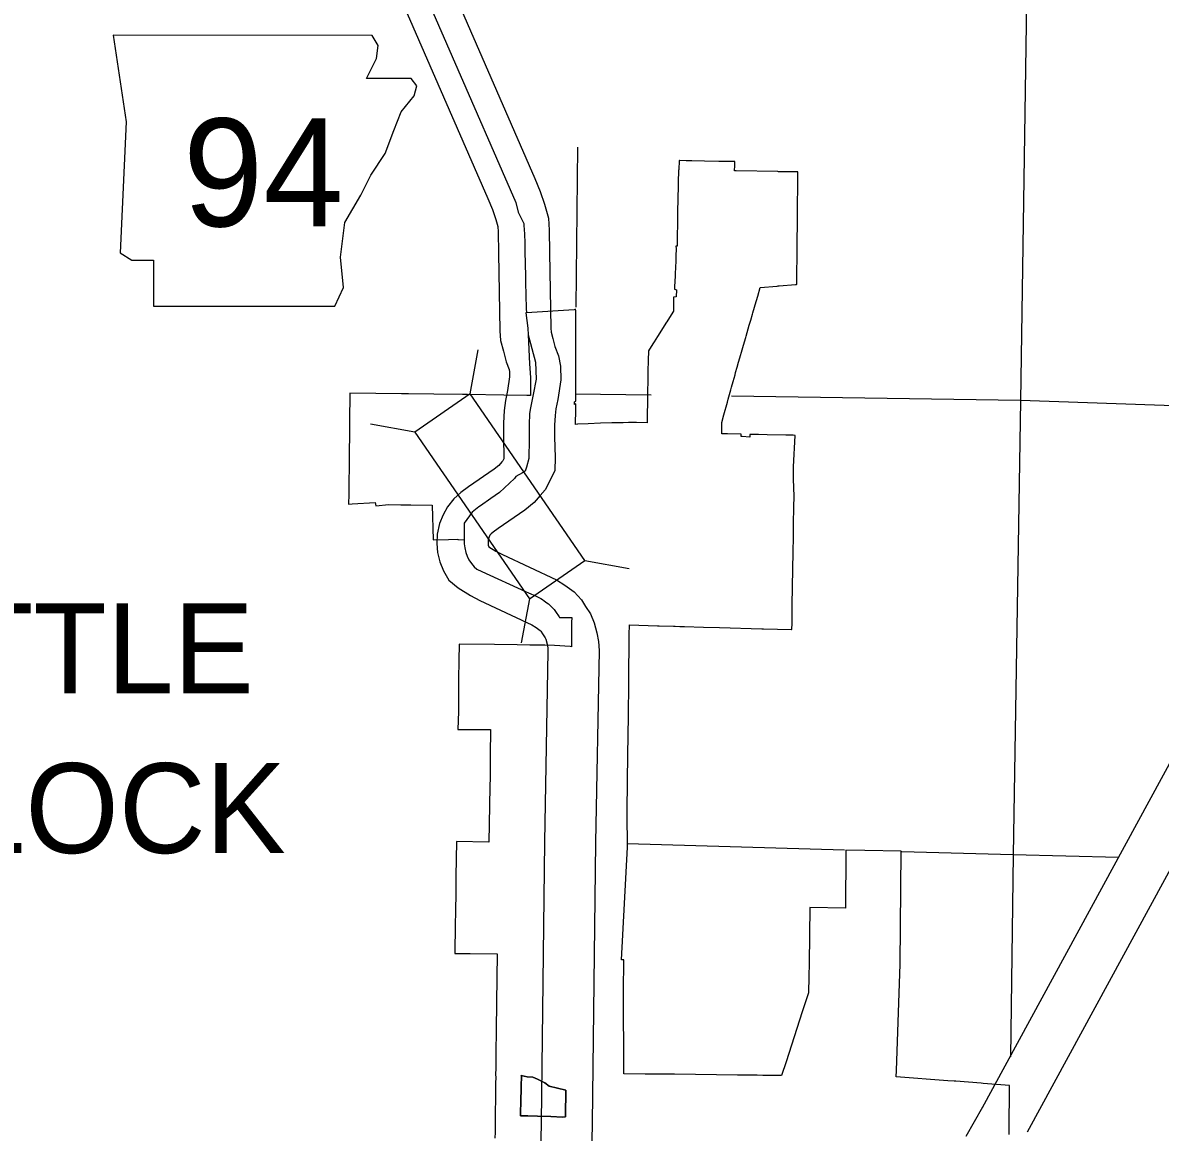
# Model space of a CAD drawing. Extents: x 309389.3 to 309420.2, y 336441.4 to 336461.2.
# Drawn here: x 309392.47 to 309393.483, y 336458.352 to 336459.339 of the extents above; entities that cross this region are included whole.
import ezdxf

# ---------------------------------------------------------------- set-up
doc = ezdxf.new("R2010")
doc.units = 0
for name, color, linetype in [('Level 24', 7, 'Continuous'), ('Level 37', 7, 'Continuous'), ('Level 4', 7, 'Continuous'), ('Level 48', 7, 'Continuous'), ('Level 62', 7, 'Continuous'), ('R_Axis Annot', 7, 'Continuous'), ('R_Contours', 7, 'Continuous')]:
    doc.layers.add(name, color=color, linetype=linetype)

msp = doc.modelspace()

# ---------------------------------------------------------------- linework, layer by layer
at = {"layer": 'Level 24'}
for points in [[(309392.8477, 336459.3808), (309392.9261, 336459.2006), (309392.9308, 336459.1891), (309392.9346, 336459.178), (309392.9382, 336459.1655), (309392.9387, 336459.1547), (309392.9391, 336459.1349), (309392.9403, 336459.0674), (309392.9406, 336459.0639), (309392.942, 336459.0584), (309392.9439, 336459.0513), (309392.947, 336459.0429), (309392.9488, 336459.0337), (309392.9492, 336459.0216), (309392.9465, 336459.004), (309392.9448, 336458.9957), (309392.9441, 336458.9897), (309392.9435, 336458.9813), (309392.9435, 336458.9709), (309392.944, 336458.9524), (309392.9439, 336458.9408), (309392.9395, 336458.9315), (309392.9353, 336458.9236), (309392.9309, 336458.9185), (309392.9255, 336458.9124), (309392.9171, 336458.9056), (309392.8933, 336458.8893), (309392.8889, 336458.886), (309392.8871, 336458.8844), (309392.8861, 336458.8832), (309392.8854, 336458.8817), (309392.8847, 336458.8801), (309392.8844, 336458.879), (309392.8844, 336458.8765), (309392.8845, 336458.8746), (309392.8845, 336458.8743), (309392.8851, 336458.8729), (309392.8913, 336458.8691), (309392.8971, 336458.8661), (309392.9454, 336458.8434), (309392.9528, 336458.8387), (309392.9609, 336458.8329), (309392.9677, 336458.8256), (309392.9712, 336458.8199), (309392.9756, 336458.8132), (309392.9787, 336458.8053), (309392.9813, 336458.7964), (309392.9827, 336458.7886), (309392.9832, 336458.7807), (309392.9799, 336458.6098), (309392.977, 336458.3599)], [(309392.8054, 336459.3642), (309392.8842, 336459.183), (309392.8882, 336459.1731), (309392.8912, 336459.1643), (309392.893, 336459.158), (309392.8933, 336459.1531), (309392.8936, 336459.1341), (309392.8949, 336459.0651), (309392.8956, 336459.0564), (309392.898, 336459.0469), (309392.9005, 336459.0376), (309392.9031, 336459.0306), (309392.9035, 336459.0286), (309392.9036, 336459.0243), (309392.9017, 336459.0119), (309392.9, 336459.0031), (309392.8988, 336458.9942), (309392.8981, 336458.9829), (309392.898, 336458.9703), (309392.8985, 336458.9521), (309392.8985, 336458.9513), (309392.8976, 336458.9495), (309392.8967, 336458.9485), (309392.894, 336458.9454), (309392.8899, 336458.9421), (309392.8671, 336458.9263), (309392.8601, 336458.9213), (309392.8538, 336458.9155), (309392.8482, 336458.9085), (309392.8443, 336458.9014), (309392.8411, 336458.8936), (309392.8391, 336458.8843), (309392.8389, 336458.8759), (309392.8393, 336458.8678), (309392.8414, 336458.8596), (309392.8448, 336458.8517), (309392.8496, 336458.8432), (309392.8579, 336458.8363), (309392.8689, 336458.8295), (309392.8771, 336458.8253), (309392.9234, 336458.8035), (309392.9273, 336458.8011), (309392.9307, 336458.7985), (309392.9313, 336458.798), (309392.9327, 336458.7956), (309392.9351, 336458.792), (309392.9357, 336458.7906), (309392.9369, 336458.7862), (309392.9375, 336458.7831), (309392.9377, 336458.7797), (309392.9345, 336458.6105), (309392.9316, 336458.3605)], [(309392.9316, 336458.3606), (309392.9286, 336458.2087), (309392.9262, 336458.0086), (309392.9229, 336457.8315)], [(309392.977, 336458.3597), (309392.9741, 336458.208), (309392.9716, 336458.0079), (309392.9688, 336457.8526)]]:
    msp.add_lwpolyline(points, dxfattribs=at)
at = {"layer": 'Level 37'}
for p, q in [((309392.8685, 336459.009), (309392.8757, 336459.0483)), ((309392.8191, 336458.975), (309392.7797, 336458.9822)), ((309392.9706, 336458.8608), (309393.0099, 336458.8536)), ((309392.9212, 336458.8267), (309392.914, 336458.7874))]:
    msp.add_line(p, q, dxfattribs=at)
msp.add_lwpolyline([(309392.8191, 336458.975), (309392.9212, 336458.8267), (309392.9706, 336458.8608), (309392.8685, 336459.009)], close=True, dxfattribs=at)
at = {"layer": 'Level 4'}
for points in [[(309393.3657, 336459.536), (309393.3641, 336459.3975), (309393.3582, 336459.0027), (309393.3517, 336458.5988), (309393.3493, 336458.4192)], [(309393.0295, 336459.008), (309392.962, 336459.0089)], [(309393.6565, 336458.9928), (309393.3584, 336459.0032), (309393.1011, 336459.0069)], [(309393.0083, 336458.6089), (309393.2016, 336458.6034)], [(309393.2527, 336458.6019), (309393.3515, 336458.5991), (309393.4458, 336458.5966)]]:
    msp.add_lwpolyline(points, dxfattribs=at)
at = {"layer": 'Level 48'}
msp.add_lwpolyline([(309392.9629, 336459.0863), (309392.9643, 336459.2285)], dxfattribs=at)
at = {"layer": 'Level 62'}
for points in [[(309392.8353, 336459.3487), (309392.8524, 336459.3093), (309392.909, 336459.1793), (309392.9113, 336459.1707), (309392.9162, 336459.1607), (309392.9161, 336459.1604), (309392.9163, 336459.1583), (309392.9165, 336459.1559), (309392.9166, 336459.1549), (309392.9167, 336459.1515), (309392.917, 336459.1431), (309392.9172, 336459.1336), (309392.9174, 336459.1267), (309392.9177, 336459.1118), (309392.9178, 336459.1081), (309392.918, 336459.0969), (309392.9182, 336459.0849), (309392.9185, 336459.0812), (309392.9181, 336459.0812), (309392.9197, 336459.0676), (309392.9202, 336459.0617), (309392.9212, 336459.0358), (309392.9223, 336459.0235), (309392.9221, 336459.0077), (309392.919, 336459.0077), (309392.8985, 336459.008), (309392.866, 336459.0084), (309392.8616, 336459.0085), (309392.836, 336459.0088), (309392.8137, 336459.0091), (309392.8073, 336459.0092), (309392.7846, 336459.0095), (309392.7615, 336459.0098), (309392.7612, 336458.9845), (309392.7607, 336458.9455), (309392.7605, 336458.929), (309392.7604, 336458.924), (309392.7604, 336458.9199), (309392.7602, 336458.911), (309392.7634, 336458.9111), (309392.7838, 336458.9124), (309392.7846, 336458.9095), (309392.796, 336458.9105), (309392.8069, 336458.9104), (309392.8121, 336458.9103), (309392.8158, 336458.9103), (309392.8345, 336458.9101), (309392.8354, 336458.8791), (309392.8492, 336458.8794), (309392.8574, 336458.8796), (309392.8574, 336458.8793), (309392.8631, 336458.8791), (309392.8631, 336458.8757), (309392.8636, 336458.8721), (309392.8645, 336458.8679), (309392.8658, 336458.8646), (309392.8674, 336458.8614), (309392.8696, 336458.858), (309392.8721, 336458.8551), (309392.8745, 336458.8531), (309392.8787, 336458.851), (309392.9177, 336458.8333), (309392.9205, 336458.8321), (309392.9226, 336458.8311), (309392.9252, 336458.83), (309392.9273, 336458.829), (309392.9301, 336458.8276), (309392.9315, 336458.8268), (309392.9328, 336458.8261), (309392.9344, 336458.825), (309392.9356, 336458.8241), (309392.9368, 336458.8232), (309392.9381, 336458.8221), (309392.9393, 336458.8211), (309392.9404, 336458.82), (309392.9415, 336458.8189), (309392.9424, 336458.8179), (309392.9431, 336458.8171), (309392.9438, 336458.8163), (309392.9445, 336458.8153), (309392.9457, 336458.8137), (309392.9466, 336458.8124), (309392.9476, 336458.8107), (309392.948, 336458.81), (309392.9589, 336458.81), (309392.9588, 336458.8056), (309392.9588, 336458.8053), (309392.9587, 336458.7954), (309392.9587, 336458.7935), (309392.9586, 336458.7838), (309392.9574, 336458.7842), (309392.9434, 336458.7852), (309392.935, 336458.7853), (309392.9217, 336458.7855), (309392.9103, 336458.7856)], [(309393.1564, 336458.8951), (309393.1566, 336458.9063), (309393.1566, 336458.9084), (309393.1568, 336458.9176), (309393.1562, 336458.9334), (309393.1563, 336458.9442), (309393.1576, 336458.9721), (309393.156, 336458.9722), (309393.1494, 336458.9723), (309393.1328, 336458.9727), (309393.1252, 336458.9728), (309393.1173, 336458.973), (309393.1173, 336458.9706), (309393.1105, 336458.971), (309393.1096, 336458.9711), (309393.1097, 336458.9733), (309393.0975, 336458.9735), (309393.0925, 336458.9735), (309393.0924, 336458.9781), (309393.0924, 336458.979), (309393.0924, 336458.9835), (309393.0943, 336458.9904), (309393.0974, 336459.0016), (309393.0981, 336459.0043), (309393.1004, 336459.0126), (309393.101, 336459.0151), (309393.1025, 336459.0201), (309393.1042, 336459.0261), (309393.1047, 336459.028), (309393.1061, 336459.0327), (309393.1074, 336459.0371), (309393.1084, 336459.041), (309393.1105, 336459.0482), (309393.1117, 336459.0523), (309393.1137, 336459.0592), (309393.1141, 336459.0604), (309393.116, 336459.067), (309393.1169, 336459.0702), (309393.1182, 336459.0746), (309393.1197, 336459.0799), (309393.1201, 336459.0811), (309393.123, 336459.0913), (309393.1233, 336459.0921), (309393.1244, 336459.096), (309393.1266, 336459.1038), (309393.127, 336459.1038), (309393.1414, 336459.105), (309393.1417, 336459.105), (309393.1427, 336459.1051), (309393.143, 336459.1052), (309393.1436, 336459.1052), (309393.158, 336459.1063), (309393.1584, 336459.1064), (309393.1587, 336459.1065), (309393.1589, 336459.1065), (309393.1592, 336459.1066), (309393.1596, 336459.1412), (309393.1596, 336459.1416), (309393.1599, 336459.1639), (309393.1601, 336459.2065), (309393.1589, 336459.2065), (309393.1586, 336459.2065), (309393.1559, 336459.2065), (309393.1434, 336459.2067), (309393.1429, 336459.2067), (309393.1423, 336459.2068), (309393.1052, 336459.2074), (309393.1038, 336459.2074), (309393.1038, 336459.2094), (309393.1039, 336459.2105), (309393.104, 336459.2157), (309393.1036, 336459.2157), (309393.0898, 336459.2159), (309393.077, 336459.2162), (309393.0657, 336459.2164), (309393.0606, 336459.2165), (309393.0548, 336459.2166), (309393.0544, 336459.2166), (309393.0541, 336459.2084), (309393.054, 336459.2081), (309393.0537, 336459.1971), (309393.0536, 336459.1968), (309393.0536, 336459.1943), (309393.0536, 336459.1939), (309393.0536, 336459.1931), (309393.0534, 336459.1839), (309393.0533, 336459.1834), (309393.0533, 336459.1811), (309393.0531, 336459.1725), (309393.0529, 336459.1604), (309393.0527, 336459.1497), (309393.0527, 336459.1491), (309393.0526, 336459.1404), (309393.0515, 336459.1404), (309393.0517, 336459.1383), (309393.0515, 336459.1316), (309393.0514, 336459.1267), (309393.0513, 336459.1221), (309393.051, 336459.1156), (309393.0509, 336459.1141)], [(309393.0509, 336459.1141), (309393.0504, 336459.1043), (309393.0503, 336459.1022), (309393.052, 336459.1016), (309393.0519, 336459.0953), (309393.0495, 336459.0951), (309393.0494, 336459.094), (309393.0494, 336459.0939), (309393.0495, 336459.0892), (309393.0495, 336459.0827), (309393.0494, 336459.0825), (309393.0444, 336459.0746), (309393.0435, 336459.0731), (309393.0433, 336459.0729), (309393.0383, 336459.0649), (309393.0372, 336459.0633), (309393.0353, 336459.0602), (309393.0322, 336459.0553), (309393.0311, 336459.0536), (309393.0271, 336459.0473), (309393.0271, 336459.0458), (309393.0271, 336459.0445), (309393.027, 336459.0417), (309393.0267, 336459.0263), (309393.0265, 336459.0174), (309393.0264, 336459.0143), (309393.0263, 336459.0098), (309393.0264, 336459.0098), (309393.0263, 336459.0086), (309393.026, 336458.984), (309393.026, 336458.9834), (309393.0165, 336458.9835), (309393.0163, 336458.9835), (309393.0149, 336458.9835), (309393.0094, 336458.9835), (309393.0046, 336458.9834), (309392.9946, 336458.9832), (309392.9844, 336458.9829), (309392.9736, 336458.9825), (309392.9644, 336458.982), (309392.9639, 336458.982), (309392.9622, 336458.9819), (309392.9624, 336458.9951), (309392.9625, 336458.9982), (309392.9625, 336458.9993), (309392.9625, 336459.0001), (309392.9613, 336458.9996), (309392.9613, 336459.0019), (309392.9626, 336459.0025), (309392.9625, 336459.0055), (309392.9626, 336459.0067), (309392.9626, 336459.0078), (309392.9626, 336459.0081), (309392.9625, 336459.0341), (309392.9624, 336459.0535), (309392.9625, 336459.0701), (309392.9626, 336459.0705), (309392.9624, 336459.0829), (309392.9623, 336459.0844), (309392.961, 336459.0839), (309392.9185, 336459.0812), (309392.9181, 336459.0812), (309392.9197, 336459.0676), (309392.9202, 336459.0617), (309392.9265, 336459.0371), (309392.9272, 336459.022), (309392.9246, 336459.0084), (309392.9219, 336458.995), (309392.9212, 336458.9912), (309392.9211, 336458.9819), (309392.921, 336458.9687), (309392.9208, 336458.9514), (309392.9185, 336458.9437), (309392.9174, 336458.9402), (309392.915, 336458.9389), (309392.909, 336458.9356), (309392.9079, 336458.9338), (309392.8946, 336458.9214), (309392.8869, 336458.916), (309392.8777, 336458.9095), (309392.8762, 336458.9084), (309392.8702, 336458.9037), (309392.8632, 336458.8941), (309392.8631, 336458.8791), (309392.8631, 336458.8757), (309392.8636, 336458.8721), (309392.8645, 336458.8679), (309392.8658, 336458.8646), (309392.8674, 336458.8614), (309392.8696, 336458.858), (309392.8721, 336458.8551), (309392.8745, 336458.8531), (309392.8787, 336458.851), (309392.9177, 336458.8333), (309392.9205, 336458.8321), (309392.9226, 336458.8311), (309392.9252, 336458.83), (309392.9273, 336458.829), (309392.9301, 336458.8276), (309392.9315, 336458.8268)], [(309393.3481, 336458.3498), (309393.3482, 336458.3636), (309393.3484, 336458.3828), (309393.3484, 336458.3936), (309393.3251, 336458.3954), (309393.3233, 336458.3956), (309393.3006, 336458.3973), (309393.2993, 336458.3974), (309393.2935, 336458.3978), (309393.2475, 336458.4014), (309393.2478, 336458.4068), (309393.2512, 336458.5014), (309393.2521, 336458.6021), (309393.2196, 336458.6027), (309393.2027, 336458.603), (309393.2027, 336458.6001), (309393.2026, 336458.5527), (309393.2026, 336458.5515), (309393.1707, 336458.5519), (309393.1701, 336458.5024), (309393.1699, 336458.4904), (309393.1697, 336458.4761), (309393.1641, 336458.4592), (309393.1497, 336458.4146), (309393.1456, 336458.4023), (309393.129, 336458.4025), (309393.124, 336458.4026), (309393.1064, 336458.4028), (309393.0503, 336458.4035), (309393.0256, 336458.4037), (309393.0242, 336458.4037), (309393.0052, 336458.4039), (309393.0053, 336458.4066), (309393.005, 336458.4768), (309393.0052, 336458.5054), (309393.0032, 336458.5055), (309393.0084, 336458.6056), (309393.0083, 336458.6357), (309393.0086, 336458.6663), (309393.0092, 336458.7063), (309393.0093, 336458.7212), (309393.0097, 336458.7527), (309393.0101, 336458.7947), (309393.0102, 336458.8035), (309393.0352, 336458.8027), (309393.0366, 336458.8027), (309393.0495, 336458.8023), (309393.0509, 336458.8022), (309393.055, 336458.8021), (309393.0553, 336458.8021), (309393.0593, 336458.802), (309393.076, 336458.8015), (309393.0903, 336458.8011), (309393.1282, 336458.8), (309393.1296, 336458.7999), (309393.1546, 336458.7992), (309393.1549, 336458.7992), (309393.155, 336458.8049), (309393.1552, 336458.8211), (309393.1555, 336458.8372), (309393.1557, 336458.853), (309393.156, 336458.8683), (309393.1562, 336458.8817), (309393.1564, 336458.8951)], [(309392.9315, 336458.8268), (309392.9328, 336458.8261), (309392.9344, 336458.825), (309392.9356, 336458.8241), (309392.9368, 336458.8232), (309392.9381, 336458.8221), (309392.9393, 336458.8211), (309392.9404, 336458.82), (309392.9415, 336458.8189), (309392.9424, 336458.8179), (309392.9431, 336458.8171), (309392.9438, 336458.8163), (309392.9445, 336458.8153), (309392.9457, 336458.8137), (309392.9466, 336458.8124), (309392.9476, 336458.8107), (309392.948, 336458.81), (309392.9589, 336458.81), (309392.9588, 336458.8056), (309392.9588, 336458.8053), (309392.9587, 336458.7954), (309392.9587, 336458.7935), (309392.9586, 336458.7838), (309392.9574, 336458.7842), (309392.9434, 336458.7852), (309392.935, 336458.7853), (309392.9217, 336458.7855), (309392.9103, 336458.7856), (309392.8902, 336458.7859), (309392.8586, 336458.7862), (309392.8584, 336458.7719), (309392.8583, 336458.7655), (309392.8582, 336458.7614), (309392.858, 336458.7265), (309392.8576, 336458.7104), (309392.8668, 336458.7104), (309392.8846, 336458.7103), (309392.8867, 336458.7103), (309392.8862, 336458.6874), (309392.8864, 336458.6761), (309392.8862, 336458.6675), (309392.886, 336458.6597), (309392.8856, 336458.6427), (309392.8851, 336458.61), (309392.8563, 336458.6107), (309392.8557, 336458.5794), (309392.8556, 336458.5614), (309392.8555, 336458.5523), (309392.8551, 336458.5326), (309392.8549, 336458.5151), (309392.8549, 336458.511), (309392.8686, 336458.5109), (309392.8924, 336458.5106), (309392.8919, 336458.4674), (309392.8915, 336458.4429), (309392.8913, 336458.4227), (309392.8913, 336458.4099), (309392.8911, 336458.4025), (309392.8912, 336458.4019), (309392.8911, 336458.3944), (309392.8911, 336458.3891), (309392.891, 336458.3838), (309392.8909, 336458.3785), (309392.8908, 336458.3732), (309392.8907, 336458.3679), (309392.8907, 336458.3626), (309392.8906, 336458.3572), (309392.8906, 336458.352), (309392.8905, 336458.3466)], [(309392.9103, 336458.7856), (309392.8902, 336458.7859), (309392.8586, 336458.7862), (309392.8584, 336458.7719), (309392.8583, 336458.7655), (309392.8582, 336458.7614), (309392.858, 336458.7265), (309392.8576, 336458.7104), (309392.8668, 336458.7104), (309392.8846, 336458.7103), (309392.8867, 336458.7103), (309392.8862, 336458.6874), (309392.8864, 336458.6761), (309392.8862, 336458.6675), (309392.886, 336458.6597), (309392.8856, 336458.6427), (309392.8851, 336458.61), (309392.8563, 336458.6107), (309392.8557, 336458.5794), (309392.8556, 336458.5614), (309392.8555, 336458.5523), (309392.8551, 336458.5326), (309392.8549, 336458.5151), (309392.8549, 336458.511), (309392.8686, 336458.5109), (309392.8924, 336458.5106), (309392.8919, 336458.4674), (309392.8915, 336458.4429), (309392.8913, 336458.4227), (309392.8913, 336458.4099), (309392.8911, 336458.4025), (309392.8912, 336458.4019), (309392.8911, 336458.3944), (309392.8911, 336458.3891), (309392.891, 336458.3838), (309392.8909, 336458.3785), (309392.8908, 336458.3732), (309392.8907, 336458.3679), (309392.8907, 336458.3626), (309392.8906, 336458.3572), (309392.8906, 336458.352), (309392.8905, 336458.3466)]]:
    msp.add_lwpolyline(points, dxfattribs=at)
for points in [[(309392.9534, 336458.3656), (309392.9534, 336458.3665), (309392.9535, 336458.3894), (309392.9388, 336458.3929), (309392.9348, 336458.3959), (309392.9285, 336458.3992), (309392.9243, 336458.4011), (309392.9192, 336458.4014), (309392.914, 336458.4023), (309392.9141, 336458.4014), (309392.9139, 336458.3936), (309392.9138, 336458.3881), (309392.9136, 336458.3825), (309392.9135, 336458.377), (309392.9133, 336458.3715), (309392.9132, 336458.3667), (309392.9199, 336458.3666), (309392.9284, 336458.3663), (309392.9403, 336458.3659), (309392.9506, 336458.3655)], [(309392.9534, 336458.3656), (309392.9506, 336458.3655), (309392.9403, 336458.3659), (309392.9284, 336458.3663), (309392.9199, 336458.3666), (309392.9132, 336458.3667), (309392.9133, 336458.3715), (309392.9135, 336458.377), (309392.9136, 336458.3825), (309392.9138, 336458.3881), (309392.9139, 336458.3936), (309392.9141, 336458.4014), (309392.914, 336458.4023), (309392.9192, 336458.4014), (309392.9243, 336458.4011), (309392.9285, 336458.3992), (309392.9348, 336458.3959), (309392.9388, 336458.3929), (309392.9535, 336458.3894), (309392.9534, 336458.3665)]]:
    msp.add_lwpolyline(points, close=True, dxfattribs=at)
at = {"layer": 'R_Axis Annot'}
for points in [[(309393.3245, 336458.3739), (309393.4948, 336458.6869)], [(309393.3645, 336458.3522), (309393.5343, 336458.6642)], [(309393.3098, 336458.3486), (309393.3248, 336458.3745)]]:
    msp.add_lwpolyline(points, dxfattribs=at)
at = {"layer": 'R_Contours'}
msp.add_lwpolyline([(309392.5506, 336459.3281), (309392.5622, 336459.2512), (309392.557, 336459.1345), (309392.5673, 336459.1281), (309392.5865, 336459.1281), (309392.5865, 336459.0871), (309392.748, 336459.0871), (309392.7557, 336459.1038), (309392.7531, 336459.1307), (309392.757, 336459.1615), (309392.7711, 336459.1858), (309392.78, 336459.2038), (309392.7929, 336459.223), (309392.8006, 336459.2435), (309392.807, 336459.2601), (309392.8185, 336459.2742), (309392.8211, 336459.2832), (309392.8159, 336459.2896), (309392.7762, 336459.2896), (309392.7852, 336459.3076), (309392.7865, 336459.3191), (309392.7811, 336459.328)], close=True, dxfattribs=at)

# ---------------------------------------------------------------- texts
at = {"layer": 'Level 62'}
for s, p in [('LITTLE', (309392.3251, 336458.7425)), ('FLOCK', (309392.3477, 336458.6004))]:
    msp.add_text(s, height=0.08, dxfattribs=at).set_placement(p)
at = {"layer": 'R_Contours'}
msp.add_text('94', height=0.096, dxfattribs=at).set_placement((309392.6129, 336459.1581))

doc.saveas('drawing.dxf')
